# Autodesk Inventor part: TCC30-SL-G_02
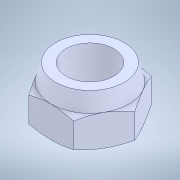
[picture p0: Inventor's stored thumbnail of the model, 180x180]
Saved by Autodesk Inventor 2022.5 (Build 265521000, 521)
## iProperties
Created: 2023-09
Part Number: TCC30-SL-G_02
Material: 一般
Document SubType Name: Modeling
Designer: ImaoCorp
Density: 1 g/cm^3
Appearance: 既定
Author: ImaoCorp
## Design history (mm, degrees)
feature "TCC30-SL-G_02"
node "ソリッド1"
